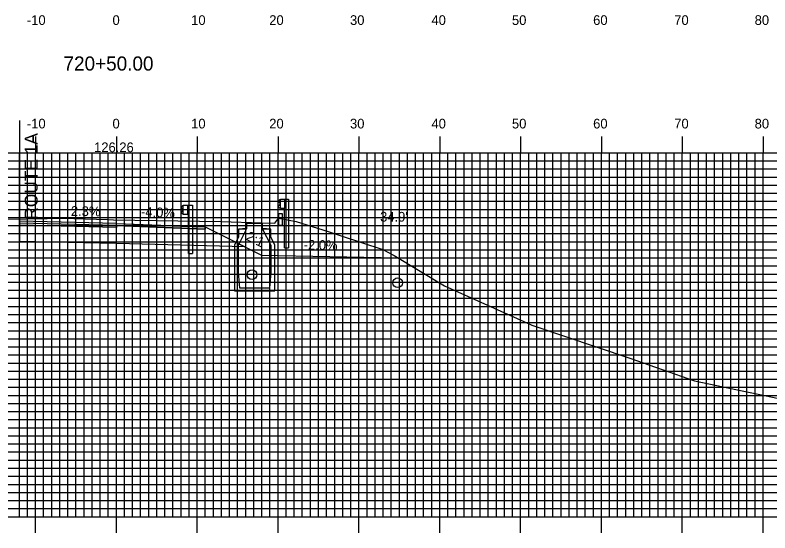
# Model space of a CAD drawing. Extents: x 858052 to 858395, y 364366 to 364586.
# Drawn here: x 858204.8 to 858298.2, y 364451.8 to 364515.8 of the extents above; entities that cross this region are included whole.
import ezdxf

# ---------------------------------------------------------------- set-up
doc = ezdxf.new("R2010")
doc.units = 0
for name, color, linetype in [('ANNOTATION', 7, 'Continuous'), ('D_Guardrail_Beam_Lt', 7, 'Continuous'), ('D_Roadway_Centerline', 7, 'Continuous'), ('D_Roadway_Centerline_Text', 7, 'Continuous'), ('D_Roadway_Edge_Shoulder', 7, 'Continuous'), ('D_Roadway_Pavement', 7, 'Continuous'), ('D_Roadway_SlopeLines', 7, 'Continuous'), ('D_Roadway_SubGrade', 7, 'Continuous'), ('D_Text_Standard', 7, 'Continuous'), ('H_V ANNOTATION', 7, 'Continuous'), ('M_Roadway_Centerline', 7, 'Continuous'), ('MAJOR', 7, 'Continuous'), ('MINOR', 7, 'Continuous'), ('S_Curb_Type_1', 7, 'Continuous'), ('S_Drainage_CB', 7, 'Continuous'), ('S_Drainage_Invert', 7, 'Continuous'), ('S_Guardrail_Beam', 7, 'Continuous'), ('S_Roadway_Centerline', 7, 'Continuous')]:
    doc.layers.add(name, color=color, linetype=linetype)

msp = doc.modelspace()

# ---------------------------------------------------------------- linework, layer by layer
at = {"layer": 'D_Guardrail_Beam_Lt'}
for p, q in [((858225.542, 364492.207), (858225.399, 364492.107)), ((858225.399, 364491.964), (858225.594, 364491.827)), ((858225.594, 364491.628), (858225.399, 364491.492)), ((858225.632, 364492.228), (858225.558, 364492.213)), ((858225.628, 364491.763), (858225.628, 364491.693)), ((858225.632, 364492.311), (858226.32, 364492.311)), ((858225.632, 364491.145), (858225.632, 364492.311)), ((858226.153, 364492.311), (858226.153, 364491.145)), ((858226.257, 364492.311), (858226.257, 364491.145)), ((858226.32, 364492.311), (858226.791, 364492.311)), ((858226.32, 364492.311), (858226.32, 364491.145)), ((858226.791, 364492.311), (858226.791, 364486.311)), ((858225.399, 364491.349), (858225.542, 364491.249)), ((858225.558, 364491.242), (858225.632, 364491.228)), ((858226.32, 364491.145), (858225.632, 364491.145)), ((858226.299, 364486.311), (858226.299, 364491.145)), ((858226.299, 364486.311), (858226.791, 364486.311))]:
    msp.add_line(p, q, dxfattribs=at)
for centre, major_axis, start_param, end_param in [((858225.449, 364492.035), (-0.0877, 0), 5.323254, 7.243116), ((858225.449, 364491.421), (-0.0877, 0), 5.323254, 7.243116), ((858225.566, 364492.173), (-0.0417, 0), 4.907132, 5.323254), ((858225.549, 364491.763), (0.0789, 0), 0, 0.959931), ((858225.549, 364491.693), (0.0789, 0), 5.323254, 6.283185), ((858225.566, 364491.283), (-0.0417, 0), 0.959931, 1.376053)]:
    msp.add_ellipse(centre, major_axis=major_axis, ratio=0.995501, start_param=start_param, end_param=end_param, dxfattribs=at)
at = {"layer": 'D_Roadway_Centerline'}
for p, q in [((858217.362, 364490.048), (858205.362, 364490.324)), ((858217.362, 364489.798), (858205.362, 364490.074)), ((858217.362, 364487.548), (858205.362, 364487.824))]:
    msp.add_line(p, q, dxfattribs=at)
msp.add_lwpolyline([(858217.362, 364489.548), (858205.39, 364489.823), (858205.362, 364489.824)], dxfattribs=at)
at = {"layer": 'D_Roadway_Edge_Shoulder'}
for points in [[(858217.362, 364490.048), (858228.362, 364489.608), (858228.362, 364489.358), (858217.362, 364489.798)], [(858217.362, 364490.048), (858225.362, 364489.728), (858225.362, 364489.728), (858228.362, 364489.608), (858228.362, 364489.358), (858217.362, 364489.798)]]:
    msp.add_lwpolyline(points, close=True, dxfattribs=at)
at = {"layer": 'D_Roadway_Pavement'}
msp.add_lwpolyline([(858217.362, 364489.798), (858217.362, 364489.548)], dxfattribs=at)
msp.add_lwpolyline([(858217.362, 364489.798), (858217.362, 364489.548)], dxfattribs=at)
msp.add_lwpolyline([(858217.362, 364489.798), (858217.362, 364489.548)], dxfattribs=at)
msp.add_lwpolyline([(858217.362, 364489.798), (858217.362, 364489.548)], dxfattribs=at)
at = {"layer": 'D_Roadway_SlopeLines'}
for points in [[(858228.362, 364489.608), (858235.295, 364486.141)], [(858235.295, 364486.141), (858252.229, 364485.802)]]:
    msp.add_lwpolyline(points, dxfattribs=at)
at = {"layer": 'D_Roadway_SubGrade'}
msp.add_line((858205.362, 364502.781), (858205.362, 364487.824), dxfattribs=at)
msp.add_line((858205.362, 364502.781), (858205.362, 364487.824), dxfattribs=at)
msp.add_lwpolyline([(858217.362, 364489.548), (858217.362, 364489.798), (858228.362, 364489.358), (858228.362, 364489.608), (858233.295, 364487.141), (858217.362, 364487.548)], close=True, dxfattribs=at)
at = {"layer": 'MAJOR'}
for p, q in [((858207.362, 364500.791), (858207.362, 364498.787)), ((858217.362, 364500.791), (858217.362, 364498.787)), ((858227.362, 364500.791), (858227.362, 364498.787)), ((858237.362, 364500.791), (858237.362, 364498.787)), ((858247.362, 364500.791), (858247.362, 364498.787)), ((858257.362, 364500.791), (858257.362, 364498.787)), ((858267.362, 364500.791), (858267.362, 364498.787)), ((858277.362, 364500.791), (858277.362, 364498.787)), ((858287.362, 364500.791), (858287.362, 364498.787)), ((858297.362, 364500.791), (858297.362, 364498.787)), ((858077.362, 364498.787), (858357.362, 364498.787)), ((858077.362, 364498.787), (858357.362, 364498.787)), ((858207.362, 364453.787), (858207.362, 364498.787)), ((858217.362, 364453.787), (858217.362, 364498.787)), ((858227.362, 364453.787), (858227.362, 364498.787)), ((858237.362, 364453.787), (858237.362, 364498.787)), ((858247.362, 364453.787), (858247.362, 364498.787)), ((858257.362, 364453.787), (858257.362, 364498.787)), ((858267.362, 364453.787), (858267.362, 364498.787)), ((858277.362, 364453.787), (858277.362, 364498.787)), ((858287.362, 364453.787), (858287.362, 364498.787)), ((858297.362, 364453.787), (858297.362, 364498.787)), ((858077.362, 364493.787), (858357.362, 364493.787)), ((858077.362, 364488.787), (858357.362, 364488.787)), ((858077.362, 364483.787), (858357.362, 364483.787)), ((858077.362, 364478.787), (858357.362, 364478.787)), ((858077.362, 364473.787), (858357.362, 364473.787)), ((858077.362, 364468.787), (858357.362, 364468.787)), ((858077.362, 364463.787), (858357.362, 364463.787)), ((858077.362, 364458.787), (858357.362, 364458.787)), ((858077.362, 364453.787), (858357.362, 364453.787)), ((858077.362, 364453.787), (858357.362, 364453.787)), ((858207.362, 364451.783), (858207.362, 364453.787)), ((858217.362, 364451.783), (858217.362, 364453.787)), ((858227.362, 364451.783), (858227.362, 364453.787)), ((858237.362, 364451.783), (858237.362, 364453.787)), ((858247.362, 364451.783), (858247.362, 364453.787)), ((858257.362, 364451.783), (858257.362, 364453.787)), ((858267.362, 364451.783), (858267.362, 364453.787)), ((858277.362, 364451.783), (858277.362, 364453.787)), ((858287.362, 364451.783), (858287.362, 364453.787)), ((858297.362, 364451.783), (858297.362, 364453.787))]:
    msp.add_line(p, q, dxfattribs=at)
at = {"layer": 'MINOR'}
for p, q in [((858205.362, 364453.787), (858205.362, 364498.787)), ((858206.362, 364453.787), (858206.362, 364498.787)), ((858208.362, 364453.787), (858208.362, 364498.787)), ((858209.362, 364453.787), (858209.362, 364498.787)), ((858210.362, 364453.787), (858210.362, 364498.787)), ((858211.362, 364453.787), (858211.362, 364498.787)), ((858212.362, 364453.787), (858212.362, 364498.787)), ((858213.362, 364453.787), (858213.362, 364498.787)), ((858214.362, 364453.787), (858214.362, 364498.787)), ((858215.362, 364453.787), (858215.362, 364498.787)), ((858216.362, 364453.787), (858216.362, 364498.787)), ((858218.362, 364453.787), (858218.362, 364498.787)), ((858219.362, 364453.787), (858219.362, 364498.787)), ((858220.362, 364453.787), (858220.362, 364498.787)), ((858221.362, 364453.787), (858221.362, 364498.787)), ((858222.362, 364453.787), (858222.362, 364498.787)), ((858223.362, 364453.787), (858223.362, 364498.787)), ((858224.362, 364453.787), (858224.362, 364498.787)), ((858225.362, 364453.787), (858225.362, 364498.787)), ((858226.362, 364453.787), (858226.362, 364498.787)), ((858228.362, 364453.787), (858228.362, 364498.787)), ((858229.362, 364453.787), (858229.362, 364498.787)), ((858230.362, 364453.787), (858230.362, 364498.787)), ((858231.362, 364453.787), (858231.362, 364498.787)), ((858232.362, 364453.787), (858232.362, 364498.787)), ((858233.362, 364453.787), (858233.362, 364498.787)), ((858234.362, 364453.787), (858234.362, 364498.787)), ((858235.362, 364453.787), (858235.362, 364498.787)), ((858236.362, 364453.787), (858236.362, 364498.787)), ((858238.362, 364453.787), (858238.362, 364498.787)), ((858239.362, 364453.787), (858239.362, 364498.787)), ((858240.362, 364453.787), (858240.362, 364498.787)), ((858241.362, 364453.787), (858241.362, 364498.787)), ((858242.362, 364453.787), (858242.362, 364498.787)), ((858243.362, 364453.787), (858243.362, 364498.787)), ((858244.362, 364453.787), (858244.362, 364498.787)), ((858245.362, 364453.787), (858245.362, 364498.787)), ((858246.362, 364453.787), (858246.362, 364498.787)), ((858248.362, 364453.787), (858248.362, 364498.787)), ((858249.362, 364453.787), (858249.362, 364498.787)), ((858250.362, 364453.787), (858250.362, 364498.787)), ((858251.362, 364453.787), (858251.362, 364498.787)), ((858252.362, 364453.787), (858252.362, 364498.787)), ((858253.362, 364453.787), (858253.362, 364498.787)), ((858254.362, 364453.787), (858254.362, 364498.787)), ((858255.362, 364453.787), (858255.362, 364498.787)), ((858256.362, 364453.787), (858256.362, 364498.787)), ((858258.362, 364453.787), (858258.362, 364498.787)), ((858259.362, 364453.787), (858259.362, 364498.787)), ((858260.362, 364453.787), (858260.362, 364498.787)), ((858261.362, 364453.787), (858261.362, 364498.787)), ((858262.362, 364453.787), (858262.362, 364498.787)), ((858263.362, 364453.787), (858263.362, 364498.787)), ((858264.362, 364453.787), (858264.362, 364498.787)), ((858265.362, 364453.787), (858265.362, 364498.787)), ((858266.362, 364453.787), (858266.362, 364498.787)), ((858268.362, 364453.787), (858268.362, 364498.787)), ((858269.362, 364453.787), (858269.362, 364498.787)), ((858270.362, 364453.787), (858270.362, 364498.787)), ((858271.362, 364453.787), (858271.362, 364498.787)), ((858272.362, 364453.787), (858272.362, 364498.787)), ((858273.362, 364453.787), (858273.362, 364498.787)), ((858274.362, 364453.787), (858274.362, 364498.787)), ((858275.362, 364453.787), (858275.362, 364498.787)), ((858276.362, 364453.787), (858276.362, 364498.787)), ((858278.362, 364453.787), (858278.362, 364498.787)), ((858279.362, 364453.787), (858279.362, 364498.787)), ((858280.362, 364453.787), (858280.362, 364498.787)), ((858281.362, 364453.787), (858281.362, 364498.787)), ((858282.362, 364453.787), (858282.362, 364498.787)), ((858283.362, 364453.787), (858283.362, 364498.787)), ((858284.362, 364453.787), (858284.362, 364498.787)), ((858285.362, 364453.787), (858285.362, 364498.787)), ((858286.362, 364453.787), (858286.362, 364498.787)), ((858288.362, 364453.787), (858288.362, 364498.787)), ((858289.362, 364453.787), (858289.362, 364498.787)), ((858290.362, 364453.787), (858290.362, 364498.787)), ((858291.362, 364453.787), (858291.362, 364498.787)), ((858292.362, 364453.787), (858292.362, 364498.787)), ((858293.362, 364453.787), (858293.362, 364498.787)), ((858294.362, 364453.787), (858294.362, 364498.787)), ((858295.362, 364453.787), (858295.362, 364498.787)), ((858296.362, 364453.787), (858296.362, 364498.787)), ((858077.362, 364497.787), (858357.362, 364497.787)), ((858077.362, 364496.787), (858357.362, 364496.787)), ((858077.362, 364495.787), (858357.362, 364495.787)), ((858077.362, 364494.787), (858357.362, 364494.787)), ((858077.362, 364492.787), (858357.362, 364492.787)), ((858077.362, 364491.787), (858357.362, 364491.787)), ((858077.362, 364490.787), (858357.362, 364490.787)), ((858077.362, 364489.787), (858357.362, 364489.787)), ((858077.362, 364487.787), (858357.362, 364487.787)), ((858077.362, 364486.787), (858357.362, 364486.787)), ((858077.362, 364485.787), (858357.362, 364485.787)), ((858077.362, 364484.787), (858357.362, 364484.787)), ((858077.362, 364482.787), (858357.362, 364482.787)), ((858077.362, 364481.787), (858357.362, 364481.787)), ((858077.362, 364480.787), (858357.362, 364480.787)), ((858077.362, 364479.787), (858357.362, 364479.787)), ((858077.362, 364477.787), (858357.362, 364477.787)), ((858077.362, 364476.787), (858357.362, 364476.787)), ((858077.362, 364475.787), (858357.362, 364475.787)), ((858077.362, 364474.787), (858357.362, 364474.787)), ((858077.362, 364472.787), (858357.362, 364472.787)), ((858077.362, 364471.787), (858357.362, 364471.787)), ((858077.362, 364470.787), (858357.362, 364470.787)), ((858077.362, 364469.787), (858357.362, 364469.787)), ((858077.362, 364467.787), (858357.362, 364467.787)), ((858077.362, 364466.787), (858357.362, 364466.787)), ((858077.362, 364465.787), (858357.362, 364465.787)), ((858077.362, 364464.787), (858357.362, 364464.787)), ((858077.362, 364462.787), (858357.362, 364462.787)), ((858077.362, 364461.787), (858357.362, 364461.787)), ((858077.362, 364460.787), (858357.362, 364460.787)), ((858077.362, 364459.787), (858357.362, 364459.787)), ((858077.362, 364457.787), (858357.362, 364457.787)), ((858077.362, 364456.787), (858357.362, 364456.787)), ((858077.362, 364455.787), (858357.362, 364455.787)), ((858077.362, 364454.787), (858357.362, 364454.787))]:
    msp.add_line(p, q, dxfattribs=at)
at = {"layer": 'S_Curb_Type_1'}
msp.add_lwpolyline([(858237.472, 364491.272), (858237.888, 364491.272), (858237.888, 364489.772), (858237.472, 364489.772)], close=True, dxfattribs=at)
msp.add_lwpolyline([(858237.472, 364491.272), (858237.888, 364491.272), (858237.888, 364489.772), (858237.472, 364489.772)], close=True, dxfattribs=at)
at = {"layer": 'S_Drainage_CB'}
for p, q in [((858233.438, 364489.354), (858232.453, 364489.354)), ((858232.453, 364489.354), (858232.453, 364488.37)), ((858232.453, 364487.353), (858233.438, 364489.354)), ((858236.456, 364489.354), (858235.439, 364489.354)), ((858235.439, 364489.354), (858236.456, 364487.353)), ((858236.456, 364488.37), (858236.456, 364489.354)), ((858232.453, 364488.37), (858231.961, 364487.353)), ((858236.948, 364487.353), (858236.456, 364488.37)), ((858231.961, 364487.353), (858231.961, 364481.71)), ((858232.453, 364484.039), (858232.453, 364487.353)), ((858236.456, 364487.353), (858236.456, 364484.039)), ((858236.948, 364481.71), (858236.948, 364487.353)), ((858232.617, 364482.038), (858232.453, 364484.039)), ((858236.456, 364484.039), (858236.292, 364482.038)), ((858231.961, 364481.71), (858236.948, 364481.71)), ((858236.292, 364482.038), (858232.617, 364482.038))]:
    msp.add_line(p, q, dxfattribs=at)
msp.add_lwpolyline([(858235.931, 364489.396), (858235.439, 364489.396), (858235.439, 364490.019), (858233.438, 364490.019), (858233.438, 364489.396), (858232.945, 364489.396)], dxfattribs=at)
at = {"layer": 'S_Drainage_Invert'}
for centre in [(858234.142, 364483.72), (858234.142, 364483.72), (858252.16, 364482.706), (858252.16, 364482.706)]:
    msp.add_circle(centre, 0.6, dxfattribs=at)
at = {"layer": 'S_Guardrail_Beam'}
for p, q in [((858237.552, 364492.952), (858237.408, 364492.852)), ((858237.552, 364492.952), (858237.408, 364492.852)), ((858237.408, 364492.709), (858237.604, 364492.573)), ((858237.408, 364492.709), (858237.604, 364492.573)), ((858237.651, 364492.974), (858237.569, 364492.959)), ((858237.651, 364492.974), (858237.569, 364492.959)), ((858237.637, 364492.509), (858237.637, 364492.418)), ((858237.637, 364492.509), (858237.637, 364492.418)), ((858237.651, 364493.047), (858238.14, 364493.047)), ((858237.651, 364491.88), (858237.651, 364493.047)), ((858237.651, 364493.047), (858238.14, 364493.047)), ((858237.651, 364491.88), (858237.651, 364493.047)), ((858238.14, 364493.047), (858238.632, 364493.047)), ((858238.14, 364493.047), (858238.14, 364491.88)), ((858238.14, 364493.047), (858238.632, 364493.047)), ((858238.14, 364493.047), (858238.14, 364491.88)), ((858238.632, 364493.047), (858238.632, 364487.047)), ((858238.632, 364493.047), (858238.632, 364487.047)), ((858237.604, 364492.353), (858237.408, 364492.217)), ((858237.604, 364492.353), (858237.408, 364492.217)), ((858237.408, 364492.074), (858237.552, 364491.974)), ((858237.408, 364492.074), (858237.552, 364491.974)), ((858237.569, 364491.967), (858237.651, 364491.953)), ((858237.569, 364491.967), (858237.651, 364491.953)), ((858238.14, 364491.88), (858237.651, 364491.88)), ((858238.14, 364491.88), (858237.651, 364491.88)), ((858238.14, 364487.047), (858238.14, 364491.88)), ((858238.14, 364487.047), (858238.14, 364491.88)), ((858238.14, 364487.047), (858238.632, 364487.047)), ((858238.14, 364487.047), (858238.632, 364487.047))]:
    msp.add_line(p, q, dxfattribs=at)
for centre, major_axis, start_param, end_param in [((858237.459, 364492.781), (-0.0877, 0), 5.323254, 7.243116), ((858237.459, 364492.781), (-0.0877, 0), 5.323254, 7.243116), ((858237.576, 364492.918), (-0.0417, 0), 4.886922, 5.323254), ((858237.576, 364492.918), (-0.0417, 0), 4.886922, 5.323254), ((858237.559, 364492.509), (0.0789, 0), 0, 0.959931), ((858237.559, 364492.509), (0.0789, 0), 0, 0.959931), ((858237.559, 364492.418), (0.0789, 0), 5.323254, 6.283185), ((858237.559, 364492.418), (0.0789, 0), 5.323254, 6.283185), ((858237.459, 364492.146), (-0.0877, 0), 5.323254, 7.243116), ((858237.459, 364492.146), (-0.0877, 0), 5.323254, 7.243116), ((858237.576, 364492.008), (-0.0417, 0), 0.959931, 1.396263), ((858237.576, 364492.008), (-0.0417, 0), 0.959931, 1.396263)]:
    msp.add_ellipse(centre, major_axis=major_axis, ratio=0.995501, start_param=start_param, end_param=end_param, dxfattribs=at)
at = {"layer": 'S_Roadway_Centerline'}
msp.add_lwpolyline([(858203.633, 364490.565), (858208.809, 364490.662), (858210.701, 364490.706), (858216.3, 364490.526), (858216.375, 364490.524), (858216.993, 364490.511), (858230.279, 364490.273), (858235.334, 364490.117), (858236.975, 364490.065), (858237.326, 364490.566), (858237.472, 364490.689), (858237.87, 364490.604), (858239.589, 364490.281), (858243.561, 364489.038), (858245.146, 364488.514), (858250.32, 364486.835), (858251.741, 364486.1), (858257.937, 364482.321), (858268.571, 364477.549), (858268.764, 364477.462), (858280.878, 364473.384), (858288.886, 364470.573), (858301.065, 364468.047)], dxfattribs=at)

# ---------------------------------------------------------------- texts
at = {"layer": 'ANNOTATION'}
for s, height, rotation, p in [('ROUTE 1A', 1.6, 90, (858207.622, 364490.516)), ('ROUTE 1A', 1.6, 90, (858207.622, 364490.516)), ('2.3%', 1.2, 359.00498, (858211.723, 364490.988)), ('-4.0%', 1.2, 357.70939, (858220.391, 364490.904)), ('2:1', 1.2, 333.43495, (858233.297, 364488.06)), ('-2.0%', 1.2, 358.85424, (858240.516, 364486.819))]:
    msp.add_text(s, height=height, rotation=rotation, dxfattribs=at).set_placement(p)
at = {"layer": 'D_Roadway_Centerline_Text'}
msp.add_text('126.26', height=1.2, dxfattribs=at).set_placement((858214.601, 364498.858))
at = {"layer": 'D_Text_Standard'}
msp.add_text("34.9'", height=1.2, dxfattribs=at).set_placement((858249.983, 364490.272))
at = {"layer": 'H_V ANNOTATION'}
for s, height, p in [('-10', 1.2, (858206.291, 364514.587)), ('0', 1.2, (858216.88, 364514.587)), ('10', 1.2, (858226.612, 364514.587)), ('20', 1.2, (858236.27, 364514.587)), ('30', 1.2, (858246.259, 364514.587)), ('40', 1.2, (858256.334, 364514.587)), ('50', 1.2, (858266.291, 364514.587)), ('60', 1.2, (858276.334, 364514.587)), ('70', 1.2, (858286.366, 364514.587)), ('80', 1.2, (858296.312, 364514.587)), ('720+50.00', 1.75, (858210.822, 364508.943)), ('-10', 1.2, (858206.291, 364501.787)), ('0', 1.2, (858216.88, 364501.787)), ('10', 1.2, (858226.612, 364501.787)), ('20', 1.2, (858236.27, 364501.787)), ('30', 1.2, (858246.259, 364501.787)), ('40', 1.2, (858256.334, 364501.787)), ('50', 1.2, (858266.291, 364501.787)), ('60', 1.2, (858276.334, 364501.787)), ('70', 1.2, (858286.366, 364501.787)), ('80', 1.2, (858296.312, 364501.787))]:
    msp.add_text(s, height=height, dxfattribs=at).set_placement(p)
at = {"layer": 'M_Roadway_Centerline'}
for s, p in [('C', (858210.696, 364490.706)), ('L', (858210.701, 364490.698))]:
    msp.add_text(s, height=0.0146, dxfattribs=at).set_placement(p)

doc.saveas('drawing.dxf')
